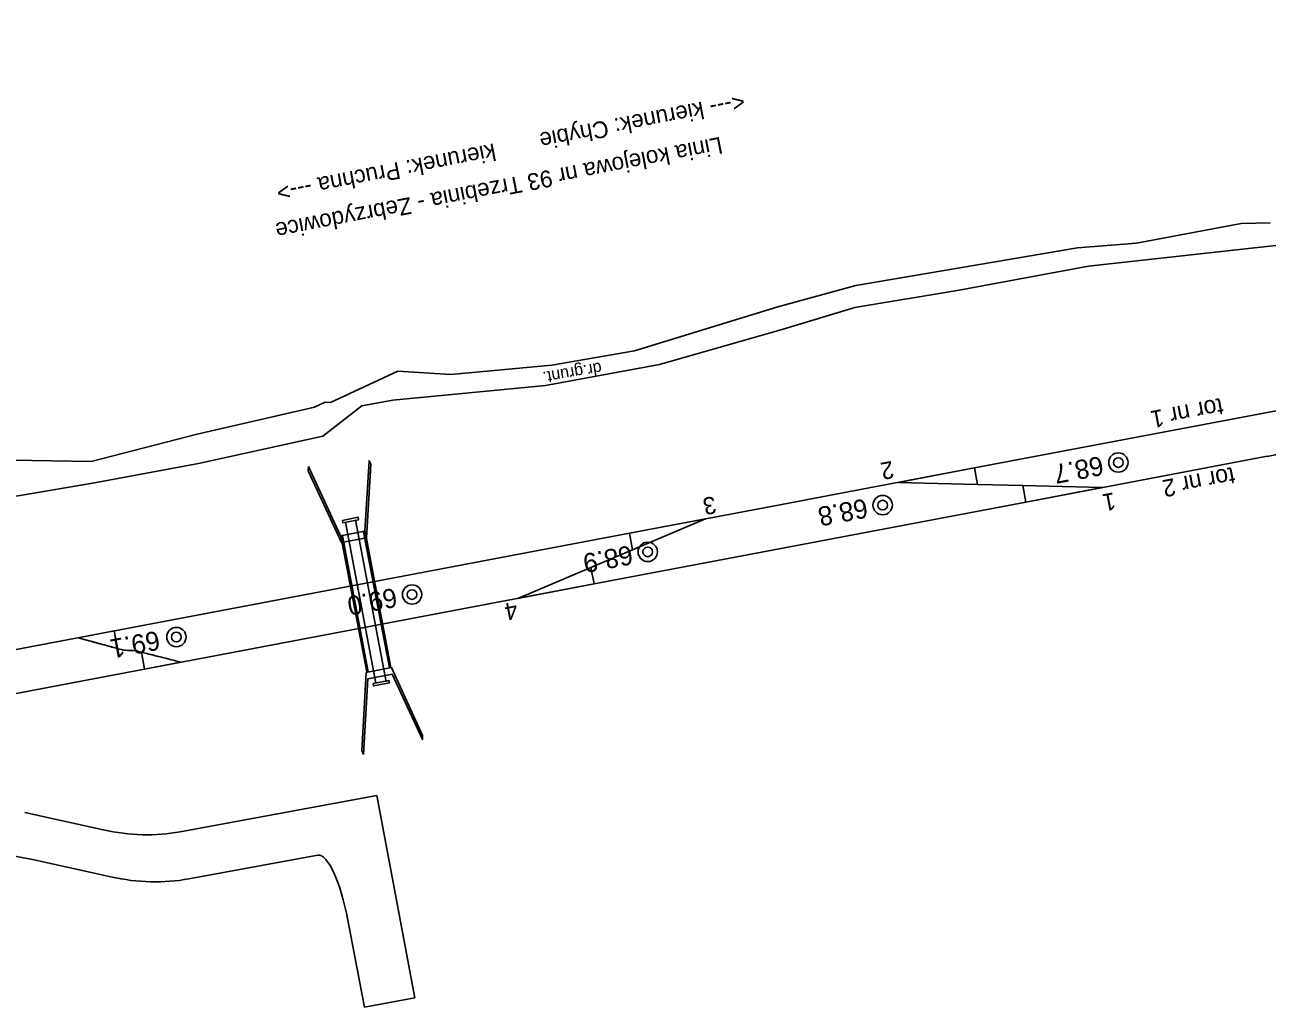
# Model space of a CAD drawing. Extents: x 6541740 to 6556805, y 5525233 to 5530361.
# Drawn here: x 6555318.7 to 6555448.4, y 5525771.9 to 5525874.4 of the extents above; entities that cross this region are included whole.
import ezdxf

# ---------------------------------------------------------------- set-up
doc = ezdxf.new("R2010")
doc.units = 0
for name, color, linetype in [('Default', 7, 'Continuous'), ('TOR_PS_OPIS_T-numeracja torow i rozjazdow', 7, 'Continuous'), ('TOR_SCH-hektometry', 7, 'Continuous'), ('TOR_SCH-obiekty istniejace', 7, 'Continuous'), ('TOR_SCH-obiekty projektowane', 7, 'Continuous'), ('TOR_SCH-opisy dodatkowe', 7, 'Continuous'), ('TOR_SCH-przejazdy+drogi istniejace', 7, 'Continuous'), ('TOR_SCH-przejazdy+drogi projektowane', 7, 'Continuous'), ('TOR_SCH-tory i rozjazdy do rozbiorki', 7, 'Continuous'), ('TOR_SCH-tory projektowane', 7, 'Continuous')]:
    doc.layers.add(name, color=color, linetype=linetype)

# ---------------------------------------------------------------- blocks, each defined once
blk = doc.blocks.new('4010_1')
at = {"layer": 'Default'}
for radius in [0.75, 0.375]:
    blk.add_circle((0, 0), radius, dxfattribs=at)

msp = doc.modelspace()

# ---------------------------------------------------------------- linework, layer by layer
at = {"layer": 'TOR_SCH-obiekty istniejace'}
for p, q in [((6555355.37, 5525805.72), (6555352.2, 5525822.5)), ((6555356.44, 5525805.85), (6555353.25, 5525822.74))]:
    msp.add_line(p, q, dxfattribs=at)
for points in [[(6555351.86, 5525822.7), (6555353.52, 5525823.02), (6555353.56, 5525822.76), (6555351.91, 5525822.45)], [(6555355.08, 5525805.67), (6555356.73, 5525805.98), (6555356.78, 5525805.73), (6555355.13, 5525805.41)]]:
    msp.add_lwpolyline(points, close=True, dxfattribs=at)
at = {"layer": 'TOR_SCH-obiekty projektowane'}
for p, q in [((6555354.41, 5525806.87), (6555351.72, 5525821.06)), ((6555354.56, 5525806.9), (6555351.87, 5525821.09)), ((6555356.77, 5525807.32), (6555354.08, 5525821.5)), ((6555356.91, 5525807.35), (6555354.23, 5525821.53))]:
    msp.add_line(p, q, dxfattribs=at)
msp.add_lwpolyline([(6555348.34, 5525828.31), (6555348.31, 5525827.87), (6555351.76, 5525820.38), (6555354.39, 5525820.88), (6555354.83, 5525828.53), (6555354.65, 5525828.93), (6555354.22, 5525821.56), (6555351.67, 5525821.08), (6555348.34, 5525828.31)], dxfattribs=at)
msp.add_lwpolyline([(6555354.07, 5525798.27), (6555354.52, 5525806.15), (6555357.07, 5525806.63), (6555360.22, 5525799.81), (6555360.24, 5525800.25), (6555356.98, 5525807.33), (6555354.35, 5525806.83), (6555353.88, 5525798.67)], close=True, dxfattribs=at)
at = {"layer": 'TOR_SCH-przejazdy+drogi istniejace'}
for p, q in [((6555434.74, 5525851.65), (6555445.67, 5525853.7)), ((6555445.67, 5525853.7), (6555448.71, 5525853.77)), ((6555418.15, 5525849.37), (6555428.58, 5525851.17)), ((6555428.58, 5525851.17), (6555434.74, 5525851.65)), ((6555449.93, 5525851.46), (6555429.74, 5525849.25)), ((6555405.45, 5525847.22), (6555418.15, 5525849.37)), ((6555429.74, 5525849.25), (6555416.25, 5525846.72)), ((6555397.33, 5525844.99), (6555405.45, 5525847.22)), ((6555416.25, 5525846.72), (6555405.35, 5525844.92)), ((6555382.37, 5525840.39), (6555397.33, 5525844.99)), ((6555405.35, 5525844.92), (6555397.89, 5525842.65)), ((6555397.89, 5525842.65), (6555384.98, 5525838.96)), ((6555373.71, 5525838.89), (6555382.37, 5525840.39)), ((6555350.64, 5525834.99), (6555357.65, 5525838.27)), ((6555357.65, 5525838.27), (6555363.2, 5525837.94)), ((6555363.2, 5525837.94), (6555373.71, 5525838.89)), ((6555384.98, 5525838.96), (6555373.06, 5525836.78)), ((6555373.06, 5525836.78), (6555357.12, 5525835.26)), ((6555357.12, 5525835.26), (6555353.88, 5525834.64)), ((6555336.69, 5525831.7), (6555348.96, 5525834.51)), ((6555348.96, 5525834.51), (6555350.07, 5525835.05)), ((6555353.88, 5525834.64), (6555349.82, 5525831.5)), ((6555350.07, 5525835.05), (6555350.64, 5525834.99)), ((6555349.82, 5525831.5), (6555336.86, 5525828.63))]:
    msp.add_line(p, q, dxfattribs=at)
for points in [[(6555336.69, 5525831.7), (6555325.66, 5525828.85)], [(6555325.66, 5525828.85), (6555317.37, 5525829), (6555296.66, 5525824.99), (6555283.28, 5525822.19), (6555268.39, 5525819.31), (6555257.37, 5525816.94), (6555250.28, 5525816.78)], [(6555325.99, 5525826.63), (6555336.86, 5525828.63)], [(6555245.93, 5525814.97), (6555247.4, 5525814.66), (6555250.39, 5525814.05), (6555257.86, 5525814.24), (6555268.58, 5525816.61), (6555283.95, 5525819.5), (6555297.12, 5525822.42), (6555318.23, 5525825.3), (6555325.99, 5525826.63)]]:
    msp.add_lwpolyline(points, dxfattribs=at)
at = {"layer": 'TOR_SCH-przejazdy+drogi projektowane'}
for p, q in [((6555334.92, 5525790.19), (6555355.45, 5525793.98)), ((6555355.45, 5525793.98), (6555359.44, 5525772.85)), ((6555318.72, 5525792.2), (6555326.91, 5525790.39)), ((6555319.52, 5525787.29), (6555327.7, 5525785.48)), ((6555335.84, 5525785.28), (6555349.31, 5525787.76)), ((6555352.44, 5525780.97), (6555354.16, 5525771.88)), ((6555354.16, 5525771.88), (6555359.44, 5525772.85))]:
    msp.add_line(p, q, dxfattribs=at)
for centre, major_axis, start_param, end_param in [((6555279.6, 5526082.5), (-55.41, 292.3), 3.034923, 3.140391), ((6555366.83, 5525495.18), (-55.41, 292.3), 6.176516, 6.233631), ((6555350.66, 5525780.64), (-1.35, 7.12), 4.711187, 6.281983), ((6555279.6, 5526082.5), (-56.34, 297.21), 3.034923, 3.140391)]:
    msp.add_ellipse(centre, major_axis=major_axis, ratio=0.25, start_param=start_param, end_param=end_param, dxfattribs=at)
at = {"layer": 'TOR_SCH-tory i rozjazdy do rozbiorki'}
for points in [[(6555324.27, 5525810.44), (6555328.05, 5525811.16), (6555328.4, 5525809.31)], [(6555335, 5525807.89), (6555331.21, 5525807.17), (6555330.88, 5525808.94)]]:
    msp.add_lwpolyline(points, close=True, dxfattribs=at)
msp.add_open_spline([(6555324.27, 5525810.44), (6555325.43, 5525810.12), (6555326.92, 5525809.72), (6555328.4, 5525809.31), (6555329.25, 5525809.08), (6555330.04, 5525809.16), (6555330.88, 5525808.94), (6555332.36, 5525808.57), (6555333.84, 5525808.19), (6555335, 5525807.89)], degree=3, dxfattribs=at)
at = {"layer": 'TOR_SCH-tory projektowane'}
for p, q in [((6555661.88, 5525874.43), (6555417.84, 5525828.17)), ((6555448.39, 5525829.39), (6555439.12, 5525827.63)), ((6555417.84, 5525828.17), (6555401.91, 5525825.16)), ((6555409.87, 5525826.67), (6555417.84, 5525828.17)), ((6555439.12, 5525827.63), (6555423.2, 5525824.61)), ((6555422.89, 5525826.33), (6555418.15, 5525826.45)), ((6555431.16, 5525826.12), (6555423.2, 5525824.61)), ((6555401.91, 5525825.16), (6555397.74, 5525824.36)), ((6555423.2, 5525824.61), (6555378.13, 5525816.07)), ((6555397.74, 5525824.36), (6555381.82, 5525821.35)), ((6555389.78, 5525822.86), (6555381.82, 5525821.35)), ((6555381.82, 5525821.35), (6555221.45, 5525790.95)), ((6555382.16, 5525819.63), (6555377.79, 5525817.78)), ((6555378.13, 5525816.07), (6555362.21, 5525813.05)), ((6555370.17, 5525814.56), (6555378.13, 5525816.07)), ((6555362.21, 5525813.05), (6555222.13, 5525786.49))]:
    msp.add_line(p, q, dxfattribs=at)
for points in [[(6555417.84, 5525828.17), (6555418.15, 5525826.45), (6555409.87, 5525826.67)], [(6555423.2, 5525824.61), (6555422.89, 5525826.33), (6555431.16, 5525826.12)], [(6555381.82, 5525821.35), (6555382.16, 5525819.63), (6555389.78, 5525822.86)], [(6555378.13, 5525816.07), (6555377.79, 5525817.78), (6555370.17, 5525814.56)]]:
    msp.add_lwpolyline(points, dxfattribs=at)
msp.add_ellipse((6549311.9, 5558202.92), major_axis=(-6136.5, 32373.54), ratio=0.25, start_param=3.141593, end_param=3.144217, dxfattribs=at)

# ---------------------------------------------------------------- block references
at = {"layer": 'TOR_SCH-hektometry', "xscale": 1.345963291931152, "yscale": 1.345963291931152}
for p in [(6555432.86, 5525828.74), (6555408.26, 5525824.29), (6555383.74, 5525819.41), (6555359.14, 5525814.96), (6555334.54, 5525810.52)]:
    msp.add_blockref('4010_1', p, dxfattribs=at)

# ---------------------------------------------------------------- texts
at = {"layer": 'TOR_PS_OPIS_T-numeracja torow i rozjazdow'}
for s, p in [('tor nr 1', (6555443.61, 5525835.5)), ('2', (6555409.24, 5525828.93)), ('tor nr 2', (6555444.83, 5525828.29)), ('3', (6555390.69, 5525825.25)), ('1', (6555432.4, 5525825.64)), ('4', (6555369.98, 5525814.24))]:
    msp.add_text(s, height=1.8, rotation=190.7332, dxfattribs=at).set_placement(p)
at = {"layer": 'TOR_SCH-hektometry'}
for s, p in [('68.7', (6555431.09, 5525829.44)), ('68.8', (6555406.49, 5525825)), ('68.9', (6555381.96, 5525820.12)), ('69.0', (6555357.36, 5525815.67)), ('69.1', (6555332.6, 5525811.2))]:
    msp.add_text(s, height=2, rotation=190.7691, dxfattribs=at).set_placement(p)
at = {"layer": 'TOR_SCH-opisy dodatkowe'}
for s, height, rotation, p in [('<--- kierunek: Chybie', 1.75, 191.0012, (6555393.7, 5525867.27)), ('Linia kolejowa nr 93 Trzebinia - Zebrzydowice', 1.7499, 190.987, (6555391.35, 5525862.76)), ('kierunek: Pruchna --->', 1.75, 191.0012, (6555367.69, 5525862.07))]:
    msp.add_text(s, height=height, rotation=rotation, dxfattribs=at).set_placement(p)
at = {"layer": 'TOR_SCH-przejazdy+drogi istniejace'}
msp.add_text('dr.grunt.', height=1.25, rotation=189.6518, dxfattribs=at).set_placement((6555378.83, 5525839.21))

doc.saveas('drawing.dxf')
